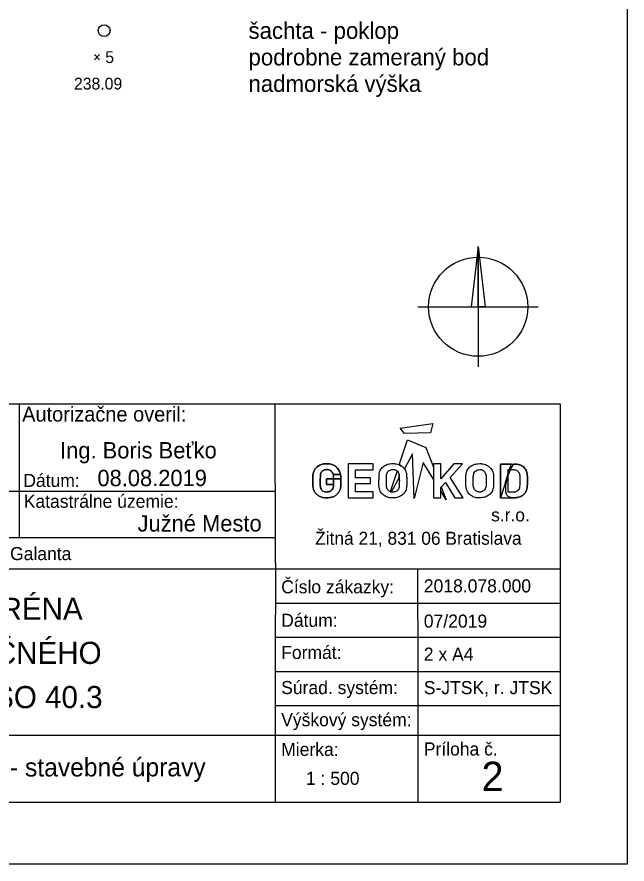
# Model space of a CAD drawing. Extents: x -264125 to -263915, y -1242307 to -1242159.
# Drawn here: x -263968.6 to -263914.6, y -1242307.4 to -1242232.4 of the extents above; entities that cross this region are included whole.
import ezdxf

# ---------------------------------------------------------------- set-up
doc = ezdxf.new("R2010")
doc.units = 0
for name, color, linetype in [('LEGENDA', 7, 'Continuous'), ('RAM_NA_TLAC_A3_1-500', 7, 'Continuous'), ('ROZPISKA', 7, 'Continuous')]:
    doc.layers.add(name, color=color, linetype=linetype)

msp = doc.modelspace()

# ---------------------------------------------------------------- linework, layer by layer
at = {"layer": 'LEGENDA'}
for p, q in [((-263961.743, -1242236.142), (-263961.281, -1242235.68)), ((-263961.281, -1242236.142), (-263961.743, -1242235.68))]:
    msp.add_line(p, q, dxfattribs=at)
msp.add_circle((-263960.877, -1242233.56), 0.522, dxfattribs=at)
at = {"layer": 'RAM_NA_TLAC_A3_1-500'}
msp.add_lwpolyline([(-264124.579, -1242158.913), (-263914.579, -1242158.913), (-263914.579, -1242307.413), (-264124.579, -1242307.413)], close=True, dxfattribs=at)
at = {"layer": 'ROZPISKA'}
for p, q in [((-263927.763, -1242252.699), (-263928.395, -1242258.029)), ((-263927.763, -1242252.699), (-263927.763, -1242263.359)), ((-263927.763, -1242252.699), (-263927.132, -1242258.028)), ((-263933.093, -1242258.029), (-263922.434, -1242258.028)), ((-264013.782, -1242266.64), (-263920.515, -1242266.639)), ((-263968.413, -1242266.644), (-263968.406, -1242278.488)), ((-263945.72, -1242280.755), (-263945.724, -1242266.638)), ((-263920.515, -1242266.639), (-263920.513, -1242301.933)), ((-263934.761, -1242272.031), (-263934.03, -1242269.816)), ((-263934.03, -1242269.816), (-263932.404, -1242270.505)), ((-263933.564, -1242271.074), (-263934.293, -1242272.379)), ((-263933.422, -1242275.024), (-263933.564, -1242271.074)), ((-263932.404, -1242270.505), (-263931.717, -1242272.252)), ((-263935.355, -1242271.924), (-263935.303, -1242271.922)), ((-263932.642, -1242271.823), (-263933.422, -1242275.024)), ((-263931.717, -1242273.312), (-263932.642, -1242271.823)), ((-263931.081, -1242271.962), (-263931.717, -1242271.962)), ((-263929.93, -1242271.962), (-263931.081, -1242273.267)), ((-263931.081, -1242273.267), (-263931.081, -1242271.962)), ((-263930.233, -1242273.163), (-263929.136, -1242271.962)), ((-263929.136, -1242271.962), (-263929.93, -1242271.962)), ((-263925.782, -1242274.95), (-263925.781, -1242271.97)), ((-263925.781, -1242271.97), (-263925.782, -1242274.95)), ((-263925.781, -1242271.97), (-263924.829, -1242271.971)), ((-263924.829, -1242271.971), (-263925.781, -1242271.97)), ((-263934.942, -1242272.578), (-263935.549, -1242274.418)), ((-263935.344, -1242272.457), (-263935.31, -1242272.456)), ((-263935.344, -1242272.457), (-263935.31, -1242272.456)), ((-263931.717, -1242272.252), (-263931.717, -1242273.312)), ((-263925.129, -1242272.488), (-263925.129, -1242274.432)), ((-263925.129, -1242272.488), (-263925.129, -1242274.432)), ((-263939.925, -1242272.887), (-263940.587, -1242272.887)), ((-263940.587, -1242272.887), (-263939.925, -1242272.887)), ((-263929.077, -1242274.95), (-263930.233, -1242273.163)), ((-263931.029, -1242274.002), (-263930.582, -1242275.139)), ((-264013.786, -1242274.385), (-263945.722, -1242274.386)), ((-263930.582, -1242275.139), (-263931.081, -1242274.336)), ((-263929.829, -1242274.95), (-263929.077, -1242274.95)), ((-264013.784, -1242278.488), (-263945.724, -1242278.487)), ((-263945.72, -1242280.755), (-263945.721, -1242289.835)), ((-264013.79, -1242281.267), (-263945.715, -1242281.259)), ((-263945.715, -1242281.259), (-263920.512, -1242281.259)), ((-263933.119, -1242281.263), (-263933.117, -1242290.34)), ((-263945.721, -1242284.286), (-263920.515, -1242284.291)), ((-263945.726, -1242287.311), (-263920.512, -1242287.309)), ((-263945.721, -1242289.835), (-263945.722, -1242301.929)), ((-263945.726, -1242290.336), (-263920.51, -1242290.34)), ((-263933.117, -1242290.34), (-263933.114, -1242301.931)), ((-263945.722, -1242293.363), (-263920.511, -1242293.359)), ((-264013.785, -1242295.983), (-263920.512, -1242295.979)), ((-264013.784, -1242301.933), (-263920.513, -1242301.933))]:
    msp.add_line(p, q, dxfattribs=at)
for points in [[(-263927.763, -1242252.699), (-263927.132, -1242258.028), (-263927.763, -1242258.028)], [(-263934.676, -1242268.787), (-263931.788, -1242268.372), (-263931.99, -1242269.196), (-263934.292, -1242269.271)], [(-263939.269, -1242271.948), (-263939.269, -1242274.95), (-263937.071, -1242274.95), (-263937.071, -1242274.42), (-263938.61, -1242274.42), (-263938.61, -1242273.702), (-263937.294, -1242273.702), (-263937.294, -1242273.179), (-263938.61, -1242273.179), (-263938.61, -1242272.48), (-263937.071, -1242272.48), (-263937.071, -1242271.948)]]:
    msp.add_lwpolyline(points, close=True, dxfattribs=at)
for points in [[(-263931.717, -1242271.962), (-263931.717, -1242274.95), (-263931.081, -1242274.95), (-263931.081, -1242274.057), (-263930.657, -1242273.608), (-263929.829, -1242274.95)], [(-263934.744, -1242273.187), (-263934.745, -1242273.122), (-263934.747, -1242273.039), (-263934.754, -1242272.965), (-263934.766, -1242272.892), (-263934.784, -1242272.825), (-263934.81, -1242272.751), (-263934.85, -1242272.681), (-263934.893, -1242272.625), (-263934.942, -1242272.578)], [(-263934.293, -1242272.379), (-263934.313, -1242272.352), (-263934.351, -1242272.309), (-263934.39, -1242272.272), (-263934.433, -1242272.233), (-263934.477, -1242272.198), (-263934.526, -1242272.162), (-263934.568, -1242272.135), (-263934.613, -1242272.107), (-263934.665, -1242272.076), (-263934.712, -1242272.051), (-263934.761, -1242272.031)], [(-263940.565, -1242273.771), (-263941.19, -1242273.771), (-263941.19, -1242273.275), (-263939.918, -1242273.275)], [(-263939.918, -1242273.275), (-263941.19, -1242273.275), (-263941.19, -1242273.771), (-263940.565, -1242273.771)], [(-263935.446, -1242274.445), (-263934.744, -1242273.187)], [(-263931.081, -1242274.336), (-263931.081, -1242274.057), (-263931.029, -1242274.002)], [(-263935.549, -1242274.418), (-263935.532, -1242274.424), (-263935.513, -1242274.43), (-263935.495, -1242274.435), (-263935.476, -1242274.439), (-263935.459, -1242274.443), (-263935.446, -1242274.445)]]:
    msp.add_lwpolyline(points, dxfattribs=at)
msp.add_circle((-263927.763, -1242258.029), 4.389, dxfattribs=at)
for points in [[(-263939.918, -1242273.275), (-263939.915, -1242273.654), (-263939.925, -1242273.994), (-263939.993, -1242274.296), (-263940.138, -1242274.538), (-263940.362, -1242274.742), (-263940.595, -1242274.878), (-263940.906, -1242274.956), (-263941.188, -1242274.976), (-263941.479, -1242274.956), (-263941.771, -1242274.859), (-263942.023, -1242274.694), (-263942.217, -1242274.5), (-263942.344, -1242274.237), (-263942.402, -1242273.946), (-263942.412, -1242273.751), (-263942.412, -1242273.159), (-263942.392, -1242272.838), (-263942.305, -1242272.566), (-263942.159, -1242272.333), (-263941.868, -1242272.1), (-263941.557, -1242271.964), (-263941.197, -1242271.925), (-263940.818, -1242271.954), (-263940.42, -1242272.119), (-263940.109, -1242272.411), (-263939.925, -1242272.887), (-263939.918, -1242273.275), (-263939.925, -1242272.887)], [(-263939.925, -1242272.887), (-263940.109, -1242272.411), (-263940.42, -1242272.119), (-263940.818, -1242271.954), (-263941.197, -1242271.925), (-263941.557, -1242271.964), (-263941.868, -1242272.1), (-263942.159, -1242272.333), (-263942.305, -1242272.566), (-263942.392, -1242272.838), (-263942.412, -1242273.159), (-263942.412, -1242273.751), (-263942.402, -1242273.946), (-263942.344, -1242274.237), (-263942.217, -1242274.5), (-263942.023, -1242274.694), (-263941.771, -1242274.859), (-263941.479, -1242274.956), (-263941.188, -1242274.976), (-263940.906, -1242274.956), (-263940.595, -1242274.878), (-263940.362, -1242274.742), (-263940.138, -1242274.538), (-263939.993, -1242274.296), (-263939.925, -1242273.994), (-263939.915, -1242273.654), (-263939.918, -1242273.275), (-263939.925, -1242272.887), (-263939.918, -1242273.275)], [(-263935.303, -1242271.922), (-263935.288, -1242271.922), (-263935.197, -1242271.921), (-263935.03, -1242271.961), (-263934.805, -1242272), (-263934.591, -1242272.117), (-263934.399, -1242272.251), (-263934.24, -1242272.436), (-263934.148, -1242272.645), (-263934.09, -1242272.875), (-263934.092, -1242273.237), (-263934.082, -1242273.61), (-263934.09, -1242273.975), (-263934.123, -1242274.207), (-263934.209, -1242274.399), (-263934.319, -1242274.57), (-263934.47, -1242274.701), (-263934.633, -1242274.819), (-263934.834, -1242274.9), (-263935.054, -1242274.964), (-263935.291, -1242274.979), (-263935.515, -1242274.965), (-263935.714, -1242274.947), (-263935.884, -1242274.869), (-263936.046, -1242274.776), (-263936.201, -1242274.675), (-263936.34, -1242274.53), (-263936.452, -1242274.335), (-263936.531, -1242274.097), (-263936.564, -1242273.708), (-263936.53, -1242273.343), (-263936.55, -1242272.993), (-263936.518, -1242272.794), (-263936.474, -1242272.599), (-263936.378, -1242272.426), (-263936.252, -1242272.283), (-263936.117, -1242272.156), (-263935.946, -1242272.064), (-263935.752, -1242271.978), (-263935.548, -1242271.936), (-263935.411, -1242271.927), (-263935.355, -1242271.924)], [(-263927.613, -1242271.922), (-263927.833, -1242271.937), (-263928.069, -1242271.989), (-263928.264, -1242272.071), (-263928.422, -1242272.163), (-263928.561, -1242272.286), (-263928.678, -1242272.424), (-263928.776, -1242272.603), (-263928.827, -1242272.798), (-263928.852, -1242272.987), (-263928.851, -1242273.197), (-263928.859, -1242273.842), (-263928.833, -1242274.083), (-263928.746, -1242274.349), (-263928.634, -1242274.539), (-263928.516, -1242274.662), (-263928.347, -1242274.78), (-263928.193, -1242274.867), (-263928.03, -1242274.934), (-263927.83, -1242274.964), (-263927.614, -1242274.974), (-263927.358, -1242274.954), (-263927.133, -1242274.892), (-263926.954, -1242274.815), (-263926.775, -1242274.693), (-263926.636, -1242274.565), (-263926.529, -1242274.406), (-263926.442, -1242274.201), (-263926.406, -1242273.991), (-263926.396, -1242273.73), (-263926.401, -1242273.11), (-263926.411, -1242272.869), (-263926.462, -1242272.654), (-263926.565, -1242272.434), (-263926.703, -1242272.27), (-263926.918, -1242272.112), (-263927.113, -1242272.014), (-263927.343, -1242271.958), (-263927.568, -1242271.922), (-263927.613, -1242271.922), (-263927.613, -1242271.922), (-263927.613, -1242271.922)], [(-263924.829, -1242271.971), (-263924.516, -1242271.971), (-263924.324, -1242271.981), (-263924.181, -1242272.009), (-263923.996, -1242272.073), (-263923.82, -1242272.173), (-263923.642, -1242272.337), (-263923.511, -1242272.527), (-263923.447, -1242272.703), (-263923.406, -1242272.977), (-263923.404, -1242273.113), (-263923.402, -1242273.707), (-263923.41, -1242273.902), (-263923.424, -1242274.06), (-263923.452, -1242274.229), (-263923.537, -1242274.437), (-263923.685, -1242274.629), (-263923.905, -1242274.803), (-263924.085, -1242274.882), (-263924.267, -1242274.934), (-263924.42, -1242274.95), (-263924.474, -1242274.95), (-263925.782, -1242274.95), (-263924.829, -1242271.971), (-263925.782, -1242274.95)], [(-263925.782, -1242274.95), (-263924.474, -1242274.95), (-263924.42, -1242274.95), (-263924.267, -1242274.934), (-263924.085, -1242274.882), (-263923.905, -1242274.803), (-263923.685, -1242274.629), (-263923.537, -1242274.437), (-263923.452, -1242274.229), (-263923.424, -1242274.06), (-263923.41, -1242273.902), (-263923.402, -1242273.707), (-263923.404, -1242273.113), (-263923.406, -1242272.977), (-263923.447, -1242272.703), (-263923.511, -1242272.527), (-263923.642, -1242272.337), (-263923.82, -1242272.173), (-263923.996, -1242272.073), (-263924.181, -1242272.009), (-263924.324, -1242271.981), (-263924.516, -1242271.971), (-263924.829, -1242271.971), (-263925.782, -1242274.95), (-263924.829, -1242271.971)], [(-263940.582, -1242272.887), (-263940.645, -1242272.723), (-263940.791, -1242272.563), (-263940.99, -1242272.47), (-263941.189, -1242272.456), (-263941.389, -1242272.48), (-263941.549, -1242272.572), (-263941.665, -1242272.699), (-263941.724, -1242272.835), (-263941.729, -1242273.039), (-263941.743, -1242273.262), (-263941.748, -1242273.529), (-263941.743, -1242273.845), (-263941.719, -1242274.078), (-263941.631, -1242274.263), (-263941.505, -1242274.37), (-263941.355, -1242274.433), (-263941.194, -1242274.452), (-263941.005, -1242274.442), (-263940.806, -1242274.36), (-263940.665, -1242274.224), (-263940.582, -1242274.068), (-263940.563, -1242273.889), (-263940.565, -1242273.771), (-263940.582, -1242272.887), (-263940.565, -1242273.771)], [(-263940.565, -1242273.771), (-263940.563, -1242273.889), (-263940.582, -1242274.068), (-263940.665, -1242274.224), (-263940.806, -1242274.36), (-263941.005, -1242274.442), (-263941.194, -1242274.452), (-263941.355, -1242274.433), (-263941.505, -1242274.37), (-263941.631, -1242274.263), (-263941.719, -1242274.078), (-263941.743, -1242273.845), (-263941.748, -1242273.529), (-263941.743, -1242273.262), (-263941.729, -1242273.039), (-263941.724, -1242272.835), (-263941.665, -1242272.699), (-263941.549, -1242272.572), (-263941.389, -1242272.48), (-263941.189, -1242272.456), (-263940.99, -1242272.47), (-263940.791, -1242272.563), (-263940.645, -1242272.723), (-263940.582, -1242272.887), (-263940.565, -1242273.771), (-263940.582, -1242272.887)], [(-263935.31, -1242272.456), (-263935.281, -1242272.457), (-263935.213, -1242272.458), (-263935.093, -1242272.484), (-263934.961, -1242272.553), (-263934.844, -1242272.667), (-263934.77, -1242272.835), (-263934.74, -1242273.018), (-263934.745, -1242273.222), (-263934.739, -1242273.434), (-263934.746, -1242273.653), (-263934.736, -1242273.856), (-263934.765, -1242274.027), (-263934.805, -1242274.181), (-263934.901, -1242274.318), (-263935.044, -1242274.412), (-263935.197, -1242274.453), (-263935.322, -1242274.445), (-263935.434, -1242274.452), (-263935.555, -1242274.423), (-263935.674, -1242274.35), (-263935.786, -1242274.24), (-263935.865, -1242274.078), (-263935.891, -1242273.883), (-263935.882, -1242273.646), (-263935.887, -1242273.384), (-263935.881, -1242273.131), (-263935.875, -1242272.924), (-263935.842, -1242272.762), (-263935.753, -1242272.629), (-263935.63, -1242272.529), (-263935.486, -1242272.465), (-263935.387, -1242272.459), (-263935.344, -1242272.457)], [(-263935.31, -1242272.456), (-263935.281, -1242272.457), (-263935.213, -1242272.458), (-263935.093, -1242272.484), (-263934.961, -1242272.553), (-263934.844, -1242272.667), (-263934.77, -1242272.835), (-263934.74, -1242273.018), (-263934.745, -1242273.222), (-263934.739, -1242273.434), (-263934.746, -1242273.653), (-263934.736, -1242273.856), (-263934.765, -1242274.027), (-263934.805, -1242274.181), (-263934.901, -1242274.318), (-263935.044, -1242274.412), (-263935.197, -1242274.453), (-263935.322, -1242274.445), (-263935.434, -1242274.452), (-263935.555, -1242274.423), (-263935.674, -1242274.35), (-263935.786, -1242274.24), (-263935.865, -1242274.078), (-263935.891, -1242273.883), (-263935.882, -1242273.646), (-263935.887, -1242273.384), (-263935.881, -1242273.131), (-263935.875, -1242272.924), (-263935.842, -1242272.762), (-263935.753, -1242272.629), (-263935.63, -1242272.529), (-263935.486, -1242272.465), (-263935.387, -1242272.459), (-263935.344, -1242272.457)], [(-263927.62, -1242272.456), (-263927.78, -1242272.47), (-263927.939, -1242272.537), (-263928.062, -1242272.639), (-263928.139, -1242272.757), (-263928.18, -1242272.921), (-263928.19, -1242273.1), (-263928.195, -1242273.372), (-263928.195, -1242273.679), (-263928.195, -1242273.889), (-263928.164, -1242274.078), (-263928.083, -1242274.242), (-263927.975, -1242274.35), (-263927.862, -1242274.416), (-263927.734, -1242274.447), (-263927.632, -1242274.447), (-263927.529, -1242274.447), (-263927.366, -1242274.406), (-263927.207, -1242274.299), (-263927.125, -1242274.181), (-263927.079, -1242274.032), (-263927.053, -1242273.863), (-263927.053, -1242273.669), (-263927.051, -1242273.427), (-263927.053, -1242273.208), (-263927.055, -1242273.032), (-263927.094, -1242272.817), (-263927.161, -1242272.675), (-263927.279, -1242272.557), (-263927.417, -1242272.486), (-263927.535, -1242272.46), (-263927.62, -1242272.456), (-263927.62, -1242272.456), (-263927.62, -1242272.456)], [(-263925.129, -1242274.432), (-263924.939, -1242274.433), (-263924.74, -1242274.434), (-263924.532, -1242274.431), (-263924.495, -1242274.434), (-263924.419, -1242274.417), (-263924.3, -1242274.356), (-263924.147, -1242274.25), (-263924.074, -1242274.064), (-263924.051, -1242273.865), (-263924.055, -1242273.584), (-263924.052, -1242273.266), (-263924.055, -1242273.005), (-263924.07, -1242272.83), (-263924.139, -1242272.708), (-263924.271, -1242272.583), (-263924.42, -1242272.516), (-263924.623, -1242272.487), (-263924.761, -1242272.486), (-263925.043, -1242272.49), (-263925.129, -1242272.488)], [(-263925.129, -1242274.432), (-263924.939, -1242274.433), (-263924.74, -1242274.434), (-263924.532, -1242274.431), (-263924.495, -1242274.434), (-263924.419, -1242274.417), (-263924.3, -1242274.356), (-263924.147, -1242274.25), (-263924.074, -1242274.064), (-263924.051, -1242273.865), (-263924.055, -1242273.584), (-263924.052, -1242273.266), (-263924.055, -1242273.005), (-263924.07, -1242272.83), (-263924.139, -1242272.708), (-263924.271, -1242272.583), (-263924.42, -1242272.516), (-263924.623, -1242272.487), (-263924.761, -1242272.486), (-263925.043, -1242272.49), (-263925.129, -1242272.488)]]:
    msp.add_open_spline(points, degree=3, dxfattribs=at)

# ---------------------------------------------------------------- texts
at = {"layer": 'LEGENDA'}
for s, height, p in [('šachta - poklop', 1.46953, (-263948.096, -1242234.294)), ('podrobne zameraný bod', 1.46953, (-263948.096, -1242236.646)), ('5', 1.045, (-263960.779, -1242236.433)), ('nadmorská výška', 1.46953, (-263948.096, -1242238.997)), ('238.09', 1.045, (-263963.551, -1242238.785))]:
    msp.add_text(s, height=height, dxfattribs=at).set_placement(p)
at = {"layer": 'ROZPISKA'}
for s, height, rotation, p in [('Autorizačne overil:', 1.32135, 0.00155, (-263968.137, -1242268.204)), ('Ing. Boris Beťko', 1.4498, 0.04559, (-263964.781, -1242271.478)), ('08.08.2019', 1.4488, 0.04559, (-263961.473, -1242273.932)), ('Dátum:', 1.1593, 0.00155, (-263968.036, -1242274)), ('Katastrálne územie:', 1.15934, 0.00155, (-263967.995, -1242275.847)), ('Južné Mesto', 1.4498, 0.04559, (-263957.921, -1242277.951)), ('s.r.o.', 1.1495, 0.00155, (-263926.61, -1242277.049)), ('Žitná 21, 831 06 Bratislava', 1.1495, 0.00155, (-263942.199, -1242279.12)), ('Odberateľ: Skupina AVA-stav - OHL, Puškinova 700/90, 924 01 Galanta', 1.15904, 0.00155, (-264013.251, -1242280.484)), ('Číslo zákazky:', 1.15904, 0.00155, (-263945.201, -1242283.425)), ('KOŠICKÁ FUTBALOVÁ ARÉNA', 1.95724, 0.04559, (-264000.449, -1242285.794)), ('Dátum:', 1.1593, 0.00155, (-263945.201, -1242286.391)), ('DOKUMENTÁCIA SKUTOČNÉHO', 1.95724, 0.04559, (-264001.385, -1242289.709)), ('Formát:', 1.1593, 0.00155, (-263945.201, -1242289.24)), ('Súrad. systém:', 1.15904, 0.00155, (-263945.201, -1242292.352)), ('VYHOTOVENIA STAVBY SO 40.3', 1.95724, 0.04559, (-264001.306, -1242293.624)), ('Výškový systém:', 1.15903, 0.00155, (-263945.201, -1242295.2)), ('Mierka:', 1.1593, 0.00155, (-263945.201, -1242297.832)), ('Príloha č.', 1.159, 0.00155, (-263932.574, -1242297.795)), ('SO 40.3 - Splašková kanalizácia - stavebné úpravy', 1.63063, 0.04559, (-264001.217, -1242299.68))]:
    msp.add_text(s, height=height, rotation=rotation, dxfattribs=at).set_placement(p)
for s, height, p in [('2018.078.000', 1.16099, (-263932.575, -1242283.342)), ('07/2019', 1.161, (-263932.575, -1242286.464)), ('2 x A4', 1.161, (-263932.575, -1242289.393)), ('S-JTSK, r. JTSK', 1.16099, (-263932.575, -1242292.358)), ('2', 2.612, (-263927.456, -1242300.95)), ('1 : 500', 1.161, (-263943.012, -1242300.397))]:
    msp.add_text(s, height=height, dxfattribs=at).set_placement(p)

doc.saveas('drawing.dxf')
